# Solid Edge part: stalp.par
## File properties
Author: user
Template: Iso Part.par
Last saved by: user
Revision: 7
Application: Solid Edge
Accuracy: 0.990
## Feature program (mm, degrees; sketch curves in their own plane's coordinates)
swept protrusion "SweptProtrusion_3"
sketch for "unnamed RevolvedProtrusion 1" plane through (0, 0, 0) normal (0, -1, 0) x-axis (1, 0, 0)
revolve "unnamed RevolvedProtrusion 1" add finite 360 deg
multibody boolean "unnamed MultibodyBoolean 1"
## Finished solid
Body 1: solid body, 1 face, 0 edges, 0 vertices.
  Faces by surface: sphere 1
Body 2: solid body, 3 faces, 2 edges, 0 vertices.
  Faces by surface: plane 1, sphere 1, spline 1
  Edges by curve: circle 2
Bounding box of the edges (mm; curved faces can reach further): 842.500 x 160.000 x 2954.663, from (-762.5, -80, 0) to (80, 80, 2954.6633).
Spherical faces by radius (mm): R100 x2
Planar faces by outward normal: -z 1
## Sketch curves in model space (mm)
arc centre (-833.8525, 0, 2884.6004) radius 100 from (-888.0082, 0, 2968.6668) through (-748.2182, 0, 2936.2411) to (-779.6969, 0, 2800.534)
line (-888.0082, 0, 2968.6668) -> (-779.6969, 0, 2800.534)
circle centre (0, 0, 0) radius 80
circle centre (0, 0, 2500) radius 40
circle centre (-750, 0, 2933.0127) radius 25
arc centre (-500, 0, 2500) radius 500 from (0, 0, 2500) through (-263.0657, 0, 2940.2978) to (-750, 0, 2933.0127)
line (0, 0, 0) -> (0, 0, 2500)
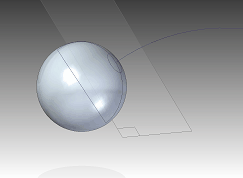
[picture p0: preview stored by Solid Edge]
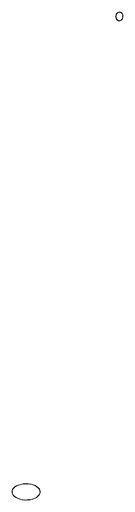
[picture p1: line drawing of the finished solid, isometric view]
